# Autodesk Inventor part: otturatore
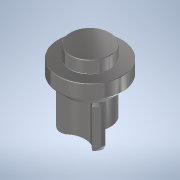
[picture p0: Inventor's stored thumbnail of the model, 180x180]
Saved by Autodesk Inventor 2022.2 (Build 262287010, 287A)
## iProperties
Created: 2014-01
Part Number: otturatore
Document SubType Name: Modeling
Designer: UTENTE
Density: 8 g/cm^3
Material: Acciaio inossidabile
Appearance: Semilucidato
Author: UTENTE
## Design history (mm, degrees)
sketch "Schizzo1"
  geometry: C1 r 6 at (0, 0); 1 further point
  constraints: 1 centre point, 1 coincident
extrude "Estrusione1" new body sketch "Schizzo1" distance "d1" = 11; taper "d2" = 0 deg
chamfer "Smusso1" distance "d3" = 0.5; stored, may be unused: second distance "d4" = 2, angle "d5" = 45 deg
sketch "Schizzo2"
  geometry: C1 r 5.5 at (0, 0) reference; C2 r 8 at (0, 0)
  constraints: 1 centre point, 1 coincident
extrude "Estrusione2" join sketch "Schizzo2" distance "d7" = 6; taper "d8" = 0 deg
sketch "Schizzo3"
  geometry: C1 r 8 at (0, 0) reference; C2 r 5 at (0, 0)
  constraints: 1 centre point, 1 coincident
extrude "Estrusione3" join sketch "Schizzo3" distance "d10" = 3; taper "d11" = 0 deg
fillet "Raccordo1" dims "d12" = 2
sketch "Schizzo4"
  geometry: L1 (-5.5, 11)-(-8, 11) reference; L2 (-8, 11)-(-8, 17) reference; L3 (-8, 17)-(-5, 17) reference; L4 (-5, 17)-(-5, 20) reference; L5 (-5, 20)-(5, 20) reference; L6 (5, 20)-(5, 17) reference; L7 (5, 17)-(8, 17) reference; L8 (8, 17)-(8, 11) reference; L9 (8, 11)-(5.5, 11) reference; L10 (5.5, 11)-(6, 10.5) reference; L11 (6, 10.5)-(6, 2) reference; L12 (4, 0)-(-4, 0) reference; L13 (-6, 2)-(-6, 10.5) reference; L14 (-6, 10.5)-(-5.5, 11) reference; L15 (-5.5, 11)-(-10.468, 15.968); L16 (-10.468, 15.968)-(-10.468, 11); L17 (-10.468, 11)-(-5.5, 11); L18 (0, -4.497)-(0, 24.083) reference; A1 r 2 centre (4, 2) between (4, 0) and (6, 2) reference; A2 r 2 centre (-4, 2) between (-6, 2) and (-4, 0) reference; 1 further point
  constraints: 6 end point, 2 perpendicular, 1 parallel
revolve "Rivoluzione1" sketch "Schizzo4" stored, may be unused: angle "d13" = 90 deg
sketch "Schizzo5"
  geometry: C1 r 5 at (-5.441, 3.141); C2 r 5 at (0, -6.283); C3 r 5 at (5.441, 3.141); 1 further point
  constraints: 3 centre point, 7 other
  dimensions: "d25" = 360 deg dimension on point (0, 0) C1.centre (derived)
extrude "Estrusione4" cut sketch "Schizzo5" distance "d27" = 11; taper "d28" = 0 deg
chamfer "Smusso2" distance "d29" = 0.1; stored, may be unused: second distance "d30" = 2, angle "d31" = 45 deg
fillet "Raccordo2" dims "d32" = 0.1
node "Solido1"
node "Proietta spigoli di taglio1"
